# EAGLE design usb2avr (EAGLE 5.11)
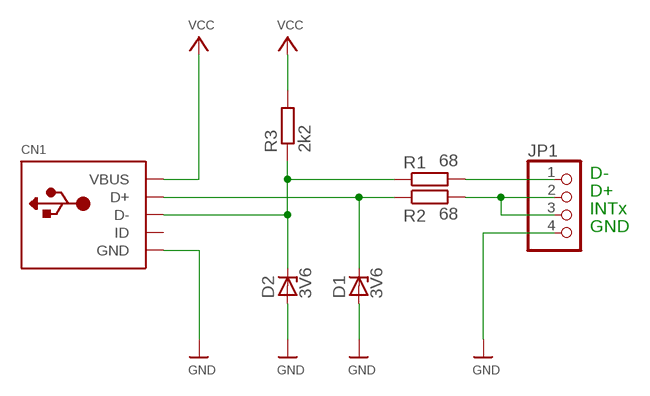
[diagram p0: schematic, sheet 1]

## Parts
CN1  USBMINIBLARGE  [USB-MINIB_LARGER]
D1  3V6  ZENER-DIODESOT23  [SOT23]
D2  3V6  ZENER-DIODESOT23  [SOT23]
JP1  PINHD-1X4  [1X04]
R1  68  R-EU_M0805  [M0805]
R2  68  R-EU_M0805  [M0805]
R3  2k2  R-EU_M0805  [M0805]

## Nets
D+: CN1.D- D2.3(C) R1.1 R3.1
D-: CN1.D+ D1.3(C) R2.1
GND: CN1.GND D1.1(A) D2.1(A) JP1.4
N$1: JP1.1 R1.2
N$2: JP1.2 JP1.3 R2.2
VCC: CN1.VBUS R3.2
Unconnected: CN1.ID

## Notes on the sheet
- D-
- D+
- INTx
- GND

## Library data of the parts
CN1 = microbuilder:USB: USB Connectors USBMINIB - Surface Mount Female Mini-B USB Connector 4UConnector: 06564
D1 D2 = diode:ZENER-DIODE: Z-Diode
JP1 = my_pinhead:PINHD-1X4: PIN HEADER
R1-R3 = rcl:R-EU_: RESISTOR, European symbol

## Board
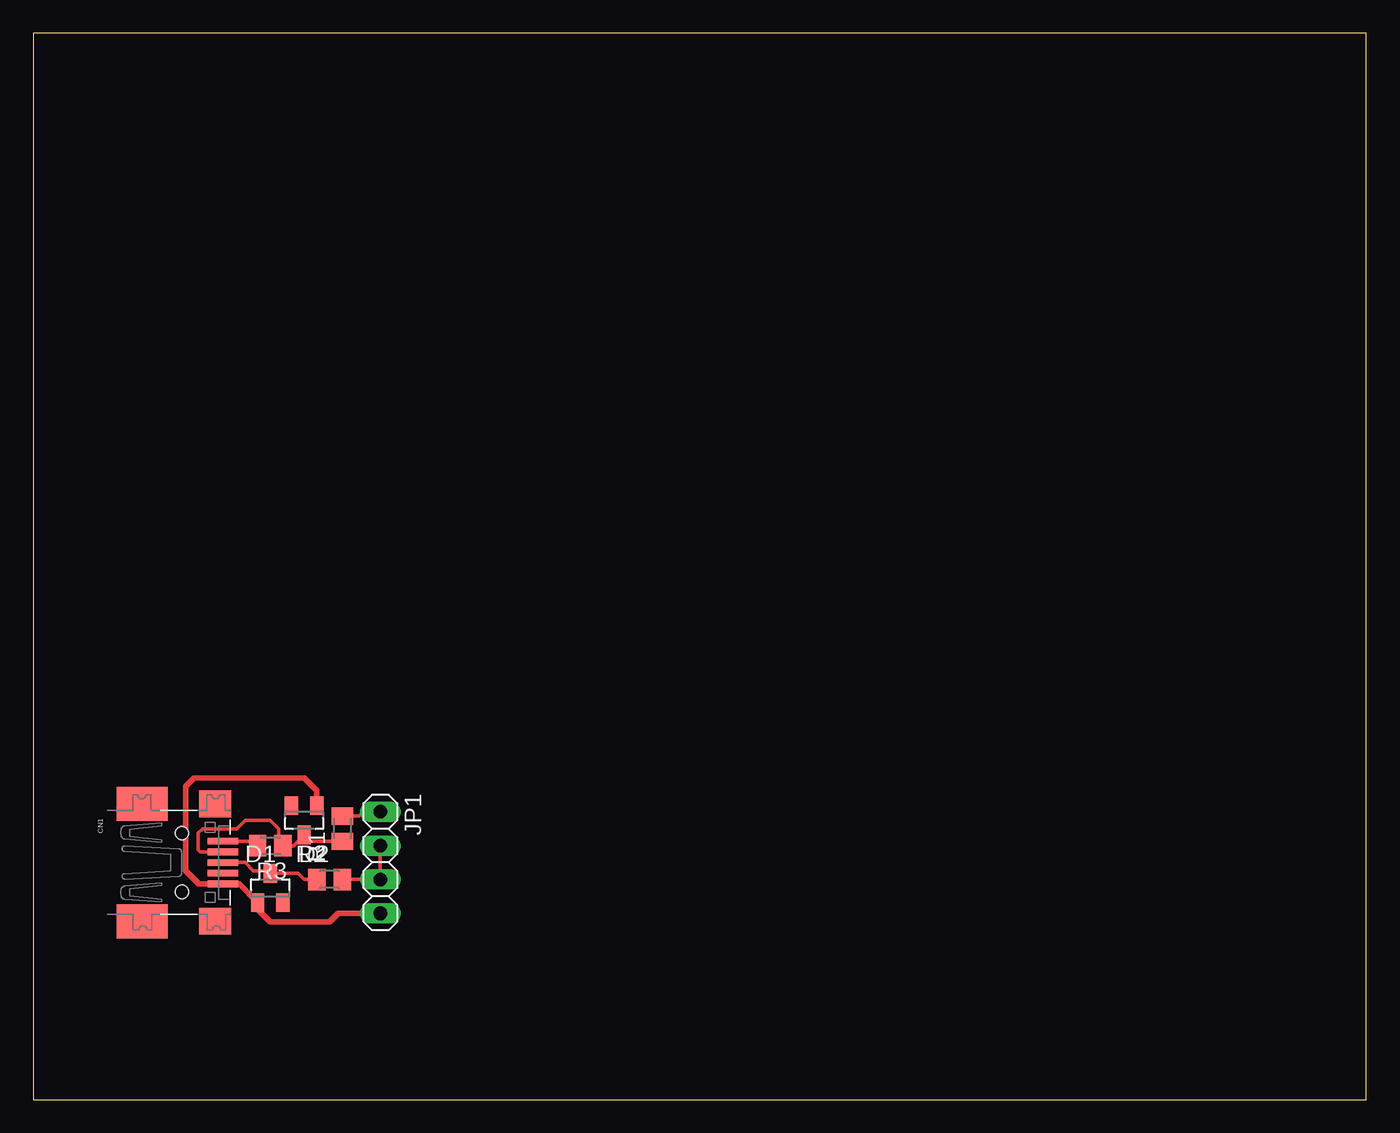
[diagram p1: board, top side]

Size 100 x 80 mm. Coordinates in mm from the lower left corner, seen from the top.
Outline: 0,0 100,0 100,80 0,80 0,0
Copper layers (1*16): Top 0.035mm / dielectric 1.5mm / Bottom 0.035mm
Design rules "default": minimum track width 10mil, minimum drill 24mil, track to track 8mil, track to pad 8mil, pad to pad 8mil, via to via 8mil, smd to smd 8mil, copper to edge 40mil, drill to drill 8mil, minimum pad ring 10mil, minimum via ring 8mil, stop-mask expansion 4mil, vias tented up to drill 0mil, thermal gap 10mil

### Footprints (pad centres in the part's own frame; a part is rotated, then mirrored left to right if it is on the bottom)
USB-MINIB_LARGER = smd 0.5 x 2.308: D+ 0,4.064; D- -0.8,4.064; GND 1.6,4.064; ID 0.8,4.064; VBUS -1.6,4.064 | smd 2.54 x 3.81: GND1 -4.4,-2; GND4 4.4,-2 | smd 2 x 2.4: GND2 -4.4,3.5; GND3 4.4,3.5 | hole 1: -2.2,1; 2.2,1
SOT23 = smd 1 x 1.4: 1 -0.95,-1.1; 2 0.95,-1.1; 3 0,1.1
1X04 = drill 1.016 long: 1 -3.81,0; 2 -1.27,0; 3 1.27,0; 4 3.81,0
M0805 = smd 1.3 x 1.6: 1 -0.95,0; 2 0.95,0

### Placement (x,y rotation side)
CN1  10.16,17.78 270 top
D1  17.78,15.88 0 top
D2  20.32,20.95 180 top
JP1  26.04,17.78 270 top
R1  23.18,20.32 90 top
R2  22.23,16.51 0 top
R3  17.78,19.05 180 top

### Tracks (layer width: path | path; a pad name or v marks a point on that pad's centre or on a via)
D+
  Top 0.254: CN1.D- 12.54,18.58 12.38,18.73 12.38,20 12.7,20.32 15.24,20.32 15.88,20.95 17.78,20.95 18.41,20.32 18.41,19.36 R3.1 19.52,19.05 D2.3 20.8,19.37 R1.1
D-
  Top 0.254: CN1.D+ 15.88,17.78 16.51,17.14 17.61,17.14 D1.3 19.86,16.98 20.32,16.51 R2.1
GND
  Top 0.406: D2.1 21.27,23.18 20.32,24.13 12.06,24.13 11.43,23.5 11.43,17.14 12.39,16.18 CN1.GND 15.43,16.18 D1.1 16.83,14.29 17.78,13.34 22.23,13.34 22.86,13.97 JP1.4
N$1
  Top 0.254: R1.2 24.45,21.27 24.77,21.59 JP1.1
N$2
  Top 0.254: R2.2 JP1.3 JP1.2
VCC
  Top 0.254: CN1.VBUS 16.5,19.38 R3.2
